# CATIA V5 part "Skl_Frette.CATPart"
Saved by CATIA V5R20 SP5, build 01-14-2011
Part number: Skl_Frette
Publications: "Plan xy", "Droite.1", "Droite.2"
Bounding box of the stored display mesh (mm): x -111.136 to 111.136, y 0 to 409.951, z -10 to 150
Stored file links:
  U:\2A\CFAO\dossier sans titre\Skl_Frette.CATPart
  U:\2A\CFAO\dossier sans titre\Skl_gouvernail.CATProduct
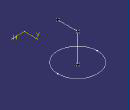
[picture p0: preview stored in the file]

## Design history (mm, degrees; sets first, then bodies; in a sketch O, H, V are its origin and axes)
Set1
  Point1 "Point.24": linked copy from another document
  Point2 "Point.23": linked copy from another document
  Point3: linked copy from another document
Set2
  Line1: type PtPt, FirstPoint Point1, SecondPoint Point2
  Line2: type PtPt, FirstPoint Point1, SecondPoint Point3
Body1 (main body)
  Sketch1 on xy-plane, origin (0, 0, 0), H (1, 0, 0), V (0, 1, 0)
    circle A1 centre (0, 298.8638) radius 111.1365
    point P1 (0, 298.8638)
    reference projected point E1 (0, 298.8638) from Point1
    reference projected point E2 (0, 187.7273) from Point3
    coincidence: P1 E1, A1 E2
